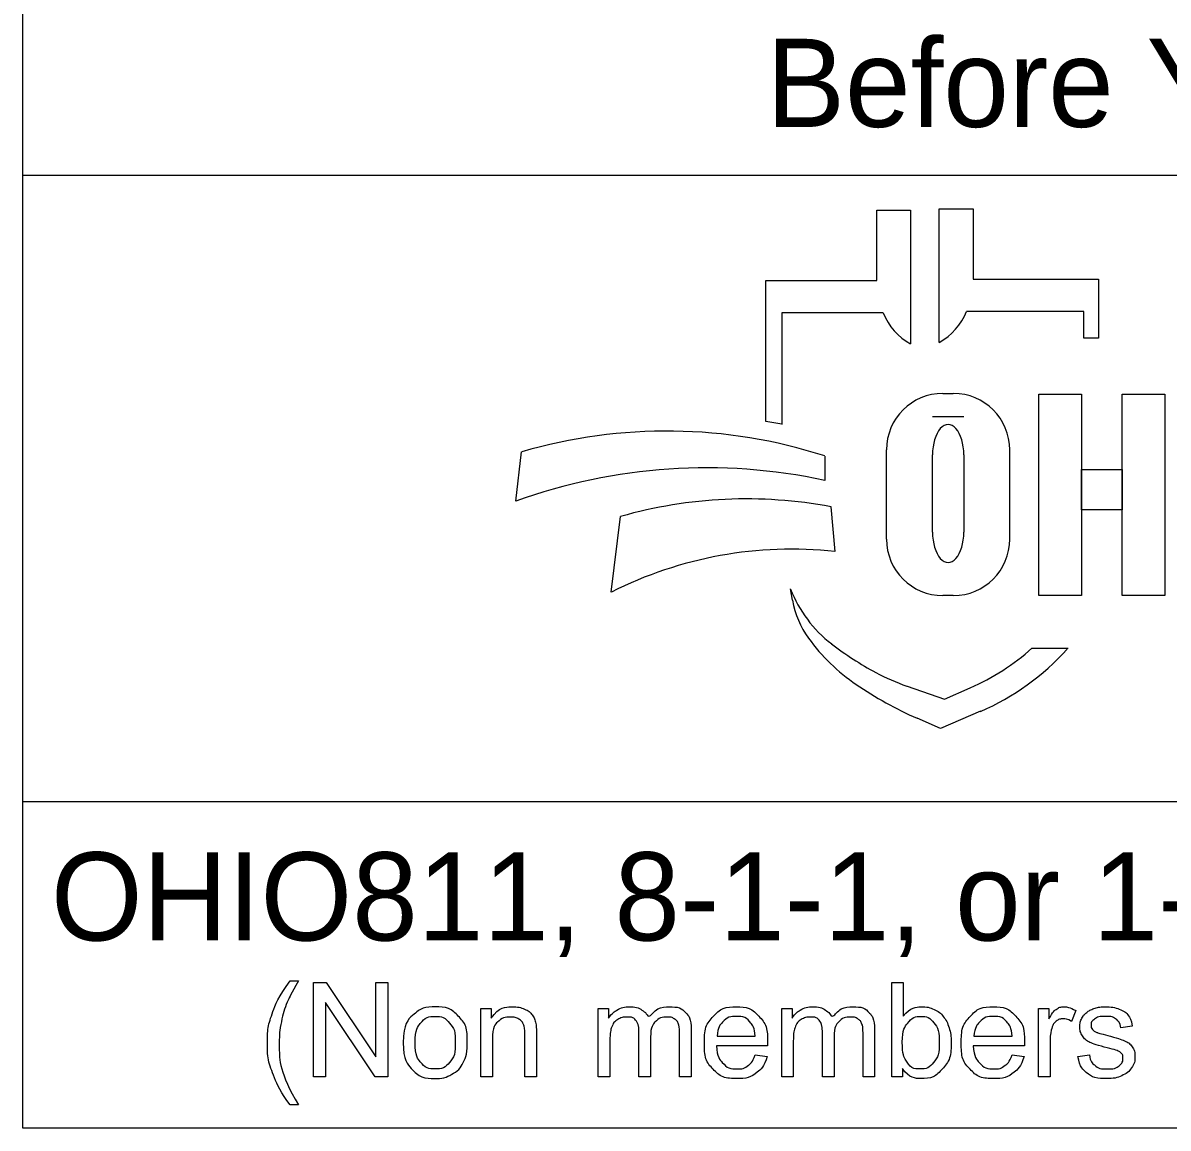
# Model space of a CAD drawing. Extents: x -8.2 to 34, y 0 to 22.
# Drawn here: x 2.978 to 4.796, y 2.143 to 3.897 of the extents above; entities that cross this region are included whole.
import ezdxf

# ---------------------------------------------------------------- set-up
doc = ezdxf.new("R2010")
doc.units = 0
doc.layers.add('SH_Data', color=7, linetype='Continuous')
doc.layers.add('SH_Text', color=7, linetype='Continuous')

msp = doc.modelspace()

# ---------------------------------------------------------------- linework, layer by layer
at = {"layer": 'SH_Data'}
for p, q in [((2.9775, 2.1428), (2.9775, 4.4803)), ((2.9775, 3.6553), (7.2275, 3.6553)), ((7.2275, 2.6607), (2.9775, 2.6607)), ((7.2275, 2.1428), (2.9775, 2.1428))]:
    msp.add_line(p, q, dxfattribs=at)
at = {"layer": 'SH_Text'}
for p, q in [((4.4329, 3.39), (4.4329, 3.6021)), ((4.4329, 3.6021), (4.4865, 3.6021)), ((4.4865, 3.6021), (4.4865, 3.4906)), ((4.3335, 3.4883), (4.3335, 3.5998)), ((4.3335, 3.5998), (4.3872, 3.5998)), ((4.3872, 3.5998), (4.3872, 3.3877)), ((4.1576, 3.2644), (4.1576, 3.4883)), ((4.1576, 3.4883), (4.3335, 3.4883)), ((4.4865, 3.4906), (4.6857, 3.4906)), ((4.6857, 3.4906), (4.6857, 3.3968)), ((4.6625, 3.4392), (4.4761, 3.4392)), ((4.6625, 3.3968), (4.6625, 3.4392)), ((4.1828, 3.4369), (4.1828, 3.26)), ((4.3439, 3.4369), (4.1828, 3.4369)), ((4.6857, 3.3968), (4.6625, 3.3968)), ((4.4385, 3.3091), (4.4551, 3.3091)), ((4.4718, 3.2721), (4.422, 3.2721)), ((4.3491, 3.0776), (4.3491, 3.2196)), ((4.5445, 3.2196), (4.5445, 3.0776)), ((3.7602, 3.1381), (3.7696, 3.2162)), ((4.2509, 3.2097), (4.2509, 3.1709)), ((4.422, 3.089), (4.422, 3.2114)), ((4.4718, 3.2114), (4.4718, 3.089)), ((4.2608, 3.1291), (4.2671, 3.0582)), ((3.912, 2.9936), (3.9267, 3.1137)), ((4.1997, 2.9807), (4.1967, 2.9986)), ((4.4551, 2.9882), (4.4385, 2.9882)), ((4.58, 2.9048), (4.6375, 2.9048)), ((4.3816, 2.8444), (4.441, 2.8239)), ((4.441, 2.8239), (4.4821, 2.8417)), ((4.4983, 2.8044), (4.435, 2.7769)), ((4.435, 2.7769), (4.3976, 2.7934))]:
    msp.add_line(p, q, dxfattribs=at)
for points in [[(4.591, 3.3081), (4.6589, 3.3081), (4.6589, 2.9881), (4.591, 2.9881)], [(4.7231, 3.3081), (4.7911, 3.3081), (4.7911, 2.9881), (4.7231, 2.9881)], [(4.6589, 3.1882), (4.7231, 3.1882), (4.7231, 3.1242), (4.6589, 3.1242)]]:
    msp.add_lwpolyline(points, close=True, dxfattribs=at)
for points in [[(3.4021, 2.3766), (3.4153, 2.3766)], [(3.4389, 2.2239), (3.4389, 2.3741), (3.4592, 2.3741), (3.5382, 2.2561), (3.5382, 2.3741), (3.5572, 2.3741), (3.5572, 2.2239), (3.5369, 2.2239), (3.4579, 2.3419), (3.4579, 2.2239), (3.4389, 2.2239)], [(4.3743, 2.2239), (4.3573, 2.2239), (4.3573, 2.3741), (4.3757, 2.3741), (4.3757, 2.3206)], [(3.7048, 2.2239), (3.7048, 2.3328), (3.7214, 2.3328), (3.7214, 2.3173)], [(3.8912, 2.2239), (3.8912, 2.3328), (3.9077, 2.3328), (3.9077, 2.3174)], [(4.1826, 2.2239), (4.1826, 2.3328), (4.1991, 2.3328), (4.1991, 2.3174)], [(4.5904, 2.2239), (4.5904, 2.3328), (4.607, 2.3328), (4.607, 2.3163)], [(4.6495, 2.3293), (4.643, 2.3122)], [(3.9743, 2.2871), (3.9743, 2.2239), (3.9559, 2.2239), (3.9559, 2.2946)], [(4.0388, 2.2986), (4.0388, 2.2239), (4.0203, 2.2239), (4.0203, 2.2924)], [(4.2657, 2.2871), (4.2657, 2.2239), (4.2473, 2.2239), (4.2473, 2.2946)], [(4.3301, 2.2986), (4.3301, 2.2239), (4.3117, 2.2239), (4.3117, 2.2924)], [(4.7394, 2.3046), (4.7213, 2.3022)], [(3.7233, 2.2833), (3.7233, 2.2239), (3.7048, 2.2239)], [(3.7932, 2.2908), (3.7932, 2.2239), (3.7748, 2.2239), (3.7748, 2.2901)], [(3.9097, 2.2803), (3.9097, 2.2239), (3.8912, 2.2239)], [(4.16, 2.2736), (4.0788, 2.2736)], [(4.0799, 2.2887), (4.1406, 2.2887)], [(4.201, 2.2803), (4.201, 2.2239), (4.1826, 2.2239)], [(4.568, 2.2736), (4.4868, 2.2736)], [(4.4879, 2.2887), (4.5486, 2.2887)], [(4.6088, 2.2809), (4.6088, 2.2239), (4.5904, 2.2239)], [(4.1404, 2.2591), (4.1595, 2.2567)], [(4.5484, 2.2591), (4.5675, 2.2567)], [(4.653, 2.2564), (4.6712, 2.2593)], [(4.3743, 2.2375), (4.3743, 2.2239)], [(3.4153, 2.1798), (3.4021, 2.1798)]]:
    msp.add_lwpolyline(points, dxfattribs=at)
for centre, radius, start, end in [((4.3847, 3.476), 0.0985, 299.2531, 338.0704), ((4.4353, 3.4736), 0.0985, 201.9296, 240.7469), ((4.4385, 3.2196), 0.0895, 90, 180), ((4.4551, 3.2196), 0.0895, 0, 90), ((4.0295, 2.4554), 0.8191, 79.2074, 81.0007), ((3.9997, 2.4302), 0.8191, 72.1402, 106.3144), ((4.0628, 2.2991), 0.8919, 77.8238, 109.8274), ((4.1267, 2.4094), 0.7322, 79.44, 105.8467), ((4.4385, 3.0776), 0.0895, 180, 270), ((4.4551, 3.0776), 0.0895, 270, 0), ((4.1987, 2.4262), 0.6357, 83.8248, 116.8021), ((4.3841, 3.0707), 0.2008, 201.0457, 232.5314), ((4.341, 3.0048), 0.1433, 189.6817, 216.0884), ((4.4747, 3.1022), 0.3088, 216.0884, 235.7167), ((4.5766, 3.3219), 0.5173, 232.5314, 241.794), ((4.3387, 3.1722), 0.3602, 293.4582, 312.0712), ((4.3387, 3.1722), 0.401, 293.4582, 317.8286), ((4.4914, 3.1631), 0.3371, 241.794, 250.9821), ((4.6412, 3.3465), 0.6044, 235.7167, 246.2325)]:
    msp.add_arc(centre, radius, start, end, dxfattribs=at)
for centre, start_param, end_param in [((4.4469, 3.2114), 4.712389, 7.853982), ((4.4469, 3.089), 1.570796, 4.712389)]:
    msp.add_ellipse(centre, major_axis=(0, 0.0484), ratio=0.514403, start_param=start_param, end_param=end_param, dxfattribs=at)
for points in [[(3.4021, 2.1798), (3.3869, 2.199), (3.3763, 2.2248), (3.3657, 2.2506), (3.3657, 2.2783), (3.3657, 2.3026), (3.3736, 2.325), (3.3829, 2.3509), (3.4021, 2.3766)], [(3.4153, 2.3766), (3.4029, 2.3553), (3.3989, 2.3462), (3.3927, 2.332), (3.3891, 2.3167), (3.3847, 2.2975), (3.3847, 2.2782), (3.3847, 2.2289), (3.4153, 2.1798)], [(3.5814, 2.2783), (3.5814, 2.3085), (3.5981, 2.3231), (3.6122, 2.3352), (3.6323, 2.3352), (3.6547, 2.3352), (3.669, 2.3205), (3.6832, 2.3058), (3.6832, 2.2799), (3.6832, 2.2589), (3.6769, 2.2469), (3.6706, 2.2348), (3.6586, 2.2282), (3.6466, 2.2215), (3.6323, 2.2215), (3.6095, 2.2215), (3.5954, 2.2362), (3.5814, 2.2508), (3.5814, 2.2783)], [(3.7214, 2.3173), (3.7334, 2.3352), (3.756, 2.3352), (3.7659, 2.3352), (3.7741, 2.3316), (3.7823, 2.3281), (3.7864, 2.3224), (3.7905, 2.3166), (3.7922, 2.3087), (3.7932, 2.3036), (3.7932, 2.2908)], [(3.9077, 2.3174), (3.9128, 2.3254), (3.9214, 2.3303), (3.9299, 2.3352), (3.9407, 2.3352), (3.9528, 2.3352), (3.9606, 2.3301), (3.9683, 2.3251), (3.9715, 2.3161), (3.9844, 2.3352), (4.0051, 2.3352), (4.0213, 2.3352), (4.03, 2.3262), (4.0388, 2.3172), (4.0388, 2.2986)], [(4.1595, 2.2567), (4.155, 2.24), (4.1428, 2.2307), (4.1306, 2.2215), (4.1117, 2.2215), (4.0878, 2.2215), (4.0738, 2.2362), (4.0598, 2.2509), (4.0598, 2.2774), (4.0598, 2.3049), (4.074, 2.32), (4.0881, 2.3352), (4.1106, 2.3352), (4.1324, 2.3352), (4.1463, 2.3203), (4.1601, 2.3055), (4.1601, 2.2785), (4.1601, 2.2769), (4.16, 2.2736)], [(4.1991, 2.3174), (4.2042, 2.3254), (4.2127, 2.3303), (4.2212, 2.3352), (4.2321, 2.3352), (4.2442, 2.3352), (4.2519, 2.3301), (4.2597, 2.3251), (4.2628, 2.3161), (4.2758, 2.3352), (4.2965, 2.3352), (4.3127, 2.3352), (4.3214, 2.3262), (4.3301, 2.3172), (4.3301, 2.2986)], [(4.3757, 2.3206), (4.3874, 2.3352), (4.4055, 2.3352), (4.4155, 2.3352), (4.4245, 2.3311), (4.4335, 2.3271), (4.4392, 2.3198), (4.445, 2.3124), (4.4483, 2.3021), (4.4516, 2.2918), (4.4516, 2.28), (4.4516, 2.252), (4.4378, 2.2368), (4.4239, 2.2215), (4.4046, 2.2215), (4.3853, 2.2215), (4.3743, 2.2375)], [(4.5675, 2.2567), (4.563, 2.24), (4.5508, 2.2307), (4.5386, 2.2215), (4.5196, 2.2215), (4.4958, 2.2215), (4.4818, 2.2362), (4.4678, 2.2509), (4.4678, 2.2774), (4.4678, 2.3049), (4.482, 2.32), (4.4961, 2.3352), (4.5186, 2.3352), (4.5404, 2.3352), (4.5543, 2.3203), (4.5681, 2.3055), (4.5681, 2.2785), (4.5681, 2.2769), (4.568, 2.2736)], [(4.607, 2.3163), (4.6133, 2.3278), (4.6187, 2.3315), (4.6241, 2.3352), (4.6305, 2.3352), (4.6398, 2.3352), (4.6495, 2.3293)], [(4.6712, 2.2593), (4.6727, 2.2483), (4.6798, 2.2425), (4.6868, 2.2366), (4.6995, 2.2366), (4.7122, 2.2366), (4.7184, 2.2418), (4.7245, 2.247), (4.7245, 2.254), (4.7245, 2.2602), (4.7191, 2.2638), (4.7153, 2.2663), (4.7002, 2.2701), (4.6799, 2.2752), (4.672, 2.2789), (4.6642, 2.2827), (4.6601, 2.2893), (4.6561, 2.2959), (4.6561, 2.3038), (4.6561, 2.3111), (4.6594, 2.3173), (4.6628, 2.3235), (4.6685, 2.3276), (4.6728, 2.3308), (4.6803, 2.333), (4.6877, 2.3352), (4.6962, 2.3352), (4.709, 2.3352), (4.7187, 2.3315), (4.7284, 2.3278), (4.733, 2.3215), (4.7377, 2.3152), (4.7394, 2.3046)], [(3.6003, 2.2783), (3.6003, 2.2574), (3.6094, 2.247), (3.6185, 2.2366), (3.6323, 2.2366), (3.646, 2.2366), (3.6551, 2.2471), (3.6642, 2.2575), (3.6642, 2.279), (3.6642, 2.2991), (3.6551, 2.3095), (3.6459, 2.3199), (3.6323, 2.3199), (3.6185, 2.3199), (3.6094, 2.3096), (3.6003, 2.2992), (3.6003, 2.2783)], [(3.7748, 2.2901), (3.7748, 2.3013), (3.7726, 2.3069), (3.7705, 2.3125), (3.765, 2.3158), (3.7595, 2.3191), (3.7521, 2.3191), (3.7404, 2.3191), (3.7318, 2.3117), (3.7233, 2.3042), (3.7233, 2.2833)], [(3.9559, 2.2946), (3.9559, 2.3069), (3.9514, 2.313), (3.9469, 2.3191), (3.9366, 2.3191), (3.9288, 2.3191), (3.9222, 2.315), (3.9156, 2.311), (3.9126, 2.3031), (3.9097, 2.2952), (3.9097, 2.2803)], [(4.0203, 2.2924), (4.0203, 2.3035), (4.0185, 2.3083), (4.0168, 2.3132), (4.012, 2.3162), (4.0073, 2.3191), (4.001, 2.3191), (3.9895, 2.3191), (3.9819, 2.3115), (3.9743, 2.3039), (3.9743, 2.2871)], [(4.1406, 2.2887), (4.1394, 2.3025), (4.1337, 2.3094), (4.1249, 2.3201), (4.1108, 2.3201), (4.0981, 2.3201), (4.0894, 2.3115), (4.0808, 2.303), (4.0799, 2.2887)], [(4.2473, 2.2946), (4.2473, 2.3069), (4.2428, 2.313), (4.2383, 2.3191), (4.228, 2.3191), (4.2202, 2.3191), (4.2136, 2.315), (4.207, 2.311), (4.204, 2.3031), (4.201, 2.2952), (4.201, 2.2803)], [(4.3117, 2.2924), (4.3117, 2.3035), (4.3099, 2.3083), (4.3081, 2.3132), (4.3034, 2.3162), (4.2987, 2.3191), (4.2923, 2.3191), (4.2809, 2.3191), (4.2733, 2.3115), (4.2657, 2.3039), (4.2657, 2.2871)], [(4.3741, 2.2792), (4.3741, 2.2596), (4.3794, 2.2509), (4.3881, 2.2366), (4.4029, 2.2366), (4.415, 2.2366), (4.4238, 2.2471), (4.4326, 2.2576), (4.4326, 2.2784), (4.4326, 2.2998), (4.4241, 2.3099), (4.4157, 2.3201), (4.4038, 2.3201), (4.3917, 2.3201), (4.3829, 2.3096), (4.3741, 2.299), (4.3741, 2.2792)], [(4.5486, 2.2887), (4.5474, 2.3025), (4.5417, 2.3094), (4.5328, 2.3201), (4.5188, 2.3201), (4.5061, 2.3201), (4.4974, 2.3115), (4.4888, 2.303), (4.4879, 2.2887)], [(4.643, 2.3122), (4.6363, 2.3162), (4.6295, 2.3162), (4.6235, 2.3162), (4.6187, 2.3125), (4.6139, 2.3089), (4.6119, 2.3024), (4.6088, 2.2926), (4.6088, 2.2809)], [(4.7213, 2.3022), (4.7201, 2.3106), (4.7142, 2.3153), (4.7083, 2.3201), (4.6975, 2.3201), (4.6848, 2.3201), (4.6794, 2.3159), (4.6739, 2.3116), (4.6739, 2.306), (4.6739, 2.3024), (4.6762, 2.2995), (4.6785, 2.2966), (4.6833, 2.2946), (4.686, 2.2936), (4.6996, 2.2899), (4.7192, 2.2847), (4.7269, 2.2813), (4.7347, 2.278), (4.7391, 2.2717), (4.7435, 2.2653), (4.7435, 2.2559), (4.7435, 2.2467), (4.7381, 2.2386), (4.7327, 2.2304), (4.7226, 2.226), (4.7124, 2.2215), (4.6996, 2.2215), (4.6784, 2.2215), (4.6672, 2.2303), (4.6561, 2.2391), (4.653, 2.2564)], [(4.0788, 2.2736), (4.0799, 2.2557), (4.089, 2.2462), (4.0981, 2.2366), (4.1117, 2.2366), (4.1219, 2.2366), (4.1291, 2.242), (4.1362, 2.2473), (4.1404, 2.2591)], [(4.4868, 2.2736), (4.4879, 2.2557), (4.497, 2.2462), (4.5061, 2.2366), (4.5197, 2.2366), (4.5299, 2.2366), (4.537, 2.242), (4.5442, 2.2473), (4.5484, 2.2591)]]:
    msp.add_open_spline(points, degree=3, dxfattribs=at)

# ---------------------------------------------------------------- texts
for s, p in [('Before You Dig', (4.1583, 3.7321)), ('OHIO811, 8-1-1, or 1-800-362-2764', (3.022, 2.4406))]:
    msp.add_text(s, height=0.14, dxfattribs=at).set_placement(p)

doc.saveas('drawing.dxf')
